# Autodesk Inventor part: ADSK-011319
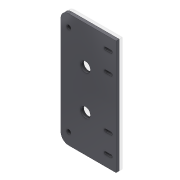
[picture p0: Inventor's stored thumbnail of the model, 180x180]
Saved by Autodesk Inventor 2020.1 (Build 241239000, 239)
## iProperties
Created: 1999-12
Part Number: ADSK-011319
Material: Acier doux
Description: PLT-44,FH,CP,03,145,070,MNT,TIMING_PULLEY
Document SubType Name: Modeling
Designer: sspink
Density: 7.86 g/cm^3
Appearance: Metal-Steel(Polish)
Mass: 4907.67 g
Surface Area: 1410.12 cm^2
Volume: 624.385 cm^3
Control State: 0
Checked Out: False
Last Check In By: sspink
Last Check In Date: 1999-12-22
Master: False
Shininess: 0.0
Length Units: 11269
Angle Units: 11279
Time Units: 11290
Mass Units: 11283
Length Display Precision: 3
Angle Display Precision: 2
Compacted: True
Dimensions: 178x368x10 mm
Mass: 4,908 kg
DocNumber: ADSK-011319.ipt
Folder: 01 - Themengebiete\Simplification\01 - Packaging machine\
VDS_Category: 3D Komponenten
Density: 0.0
Volumn: 0.0
Area: 0.0
PropertySet Name: Model Information
Author: sspink
Revision Number: -
Title: PLT-44,FH,CP,03,145,070,MNT,TIMING_PULLEY
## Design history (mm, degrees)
node "Solide1"
  node "Extrusion1" dims "d0" = 10, "d1" = 0
  node "Extrusion2" dims "d8" = 9.525, "d9" = 0
  node "Extrusion3" dims "d43" = 25.4, "d44" = 0
  node "Fillet1" dims "d52" = 25
sketch "Sketch1"
  geometry: L1 (57.172, -184)-(-120.828, -184); L2 (-120.828, 184)-(57.172, 184); L3 (57.172, -184)-(57.172, 184) reference; L4 (-95.328, -146)-(-95.328, 146); L5 (-120.828, -184)-(-120.828, 184); C1 r 6.75 at (-95.328, 146); C2 r 6.75 at (-95.328, -146); 4 further points
  constraints: 10 end point, 3 midpoint, 2 centre point, 2 horizontal alignment, 2 parallel, 2 perpendicular, 1 other
  dimensions: "d10" = 292 distance of L4.end L4.start; "d14" = 178 distance of L1.start L1.end; "d51" = 152.5 distance from line of L4.start L3; "d53" = 13.5 diameter of C1 (= d54); "d54" = 13.5 diameter of C2; "d55" = 368 distance of L1.start L2.end
sketch "Sketch2"
  geometry: L1 (-98.417, -1.225)-(57.15, -1.141) reference; L2 (57.172, 184)-(57.172, -184) reference; C1 r 16 at (-41.328, 62.306); C2 r 16 at (-41.328, -64.694)
  constraints: 2 centre point, 2 end point, 1 vertical alignment, 1 other
  dimensions: "d2" = 63.5 distance from line of C2.centre L1 (= d3); "d3" = 63.5 distance from line of C1.centre L1; "d6" = 32 diameter of C2 (= d7); "d7" = 32 diameter of C1; "d25" = 98.5 distance from line of L2 C1.centre
workplane "Arbeitsebene2"
workplane "Arbeitsebene1"
sketch "Sketch4"
  geometry: L1 (-57.172, -184)-(-57.172, 184) reference; L2 (-41.172, 141.5)-(-23.172, 141.5); L3 (-23.172, 141.5)-(-23.172, 150.5); L4 (-23.172, 150.5)-(-41.172, 150.5); L5 (-41.172, 150.5)-(-41.172, 141.5); L6 (-41.172, 78)-(-23.172, 78); L7 (-23.172, 78)-(-23.172, 87); L8 (-23.172, 87)-(-41.172, 87); L9 (-41.172, 87)-(-41.172, 78); L10 (-41.172, -87)-(-23.172, -87); L11 (-23.172, -87)-(-23.172, -78); L12 (-23.172, -78)-(-41.172, -78); L13 (-41.172, -78)-(-41.172, -87); L14 (-41.172, -150.5)-(-23.172, -150.5); L15 (-23.172, -150.5)-(-23.172, -141.5); L16 (-23.172, -141.5)-(-41.172, -141.5); L17 (-41.172, -141.5)-(-41.172, -150.5); L18 (-41.172, 146)-(-23.172, 146); L19 (-41.172, -82.5)-(-23.172, -82.5); L20 (-41.172, -146)-(-23.172, -146); L21 (-41.172, 82.5)-(-23.172, 82.5); L22 (-32.172, 146)-(-32.172, 82.5); L23 (-32.172, -82.5)-(-32.172, -146); L24 (-32.172, -82.5)-(-32.172, 82.5); A1 r 4.5 centre (-41.172, 146) between (-41.172, 150.5) and (-41.172, 141.5); A2 r 4.5 centre (-23.172, 146) between (-23.172, 141.5) and (-23.172, 150.5); A3 r 4.5 centre (-41.172, 82.5) between (-41.172, 87) and (-41.172, 78); A4 r 4.5 centre (-23.172, 82.5) between (-23.172, 78) and (-23.172, 87); A5 r 4.5 centre (-41.172, -82.5) between (-41.172, -78) and (-41.172, -87); A6 r 4.5 centre (-23.172, -82.5) between (-23.172, -87) and (-23.172, -78); A7 r 4.5 centre (-23.172, -146) between (-23.172, -150.5) and (-23.172, -141.5); A8 r 4.5 centre (-41.172, -146) between (-41.172, -141.5) and (-41.172, -150.5); 2 further points
  constraints: 46 end point, 16 point on circle, 14 equal length, 8 centre point, 8 tangent, 6 midpoint, 5 horizontal, 5 perpendicular, 3 vertical alignment, 1 horizontal alignment
  dimensions: "d37" = 9 distance between parallel lines of L4 L2; "d38" = 18 distance between parallel lines of L3 L5; "d41" = 9 distance of L6.end L7.end (= d37); "d56" = 25 distance from line of L22.start L1; "d57" = 165 distance between parallel lines of L19 L21; "d58" = 63.5 distance of L22.start L22.end; "d59" = 63.5 distance of L23.start L23.end (= d58)
node "Corps solides"
node "Corps surfaciques"
